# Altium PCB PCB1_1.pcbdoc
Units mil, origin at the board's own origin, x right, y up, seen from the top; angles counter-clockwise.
Board outline 85455 x 37379.02 mil, 2 copper layers (Top Layer, Bottom Layer); 14 components, 17 nets, 60 pads, 2 vias.
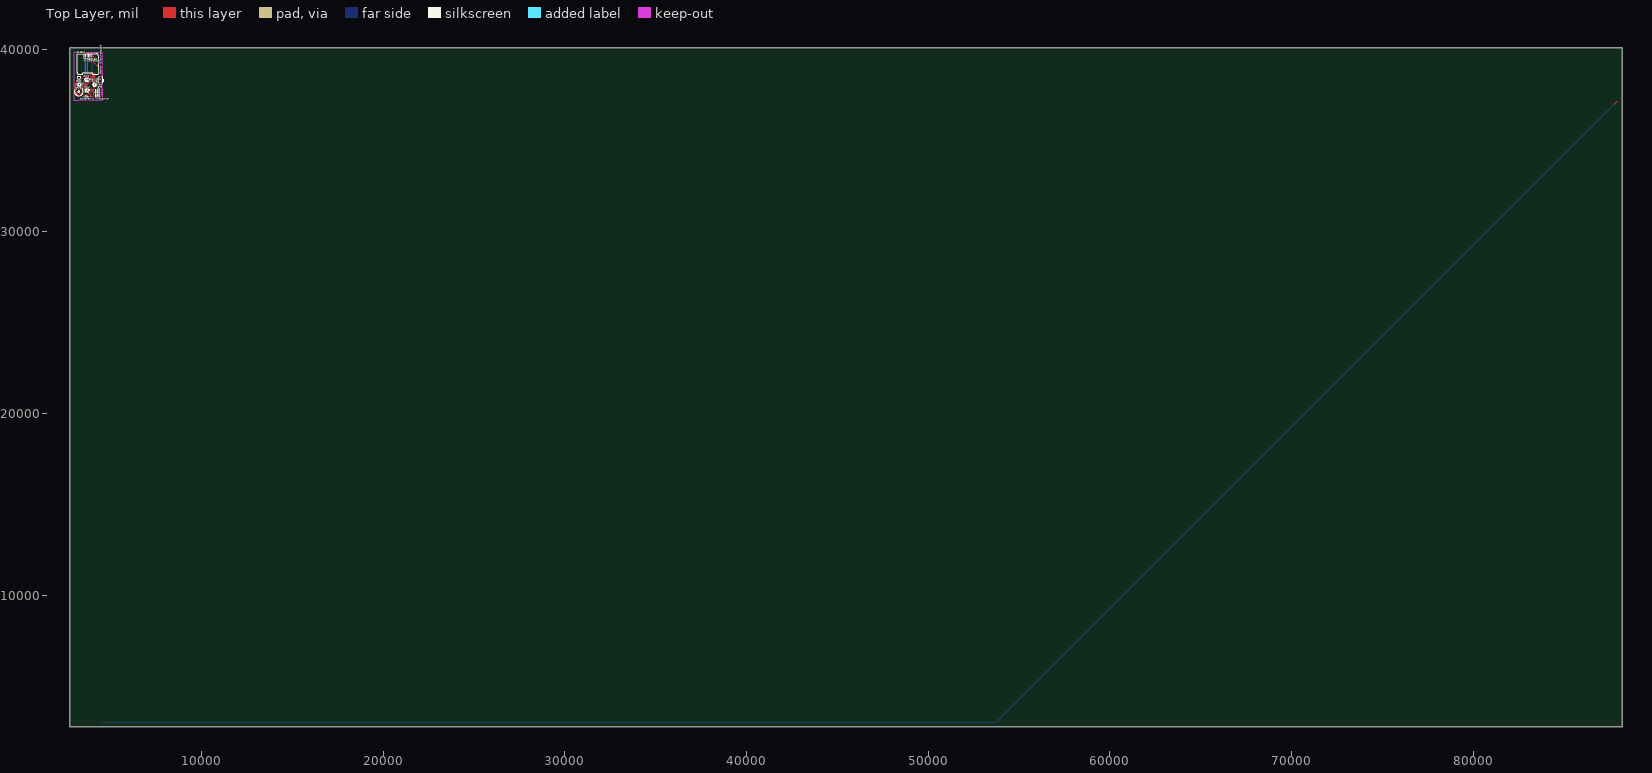
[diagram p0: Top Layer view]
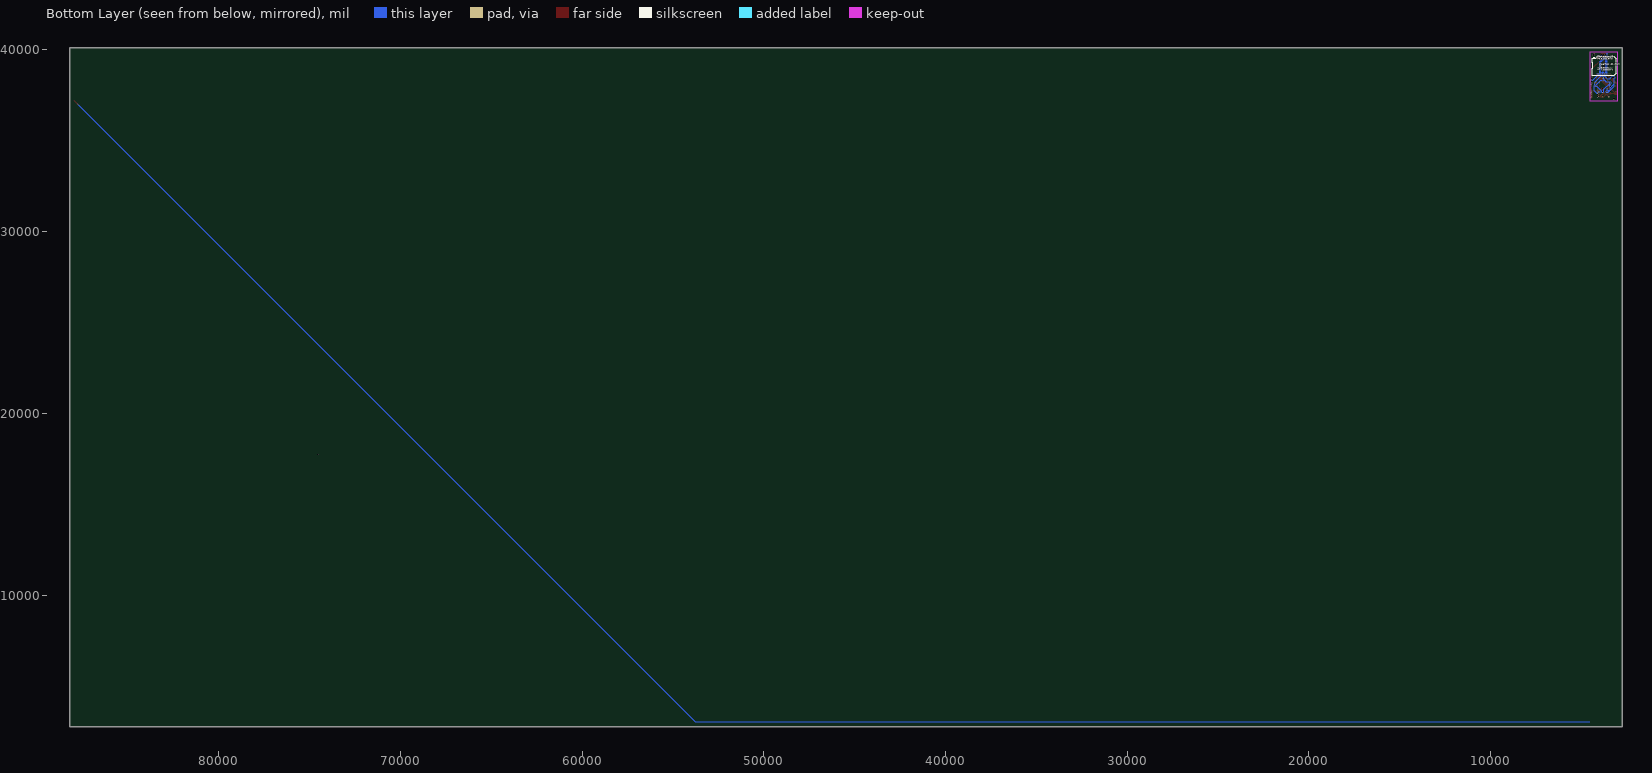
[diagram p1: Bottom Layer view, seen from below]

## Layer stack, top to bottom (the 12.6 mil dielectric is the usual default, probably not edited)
Top Layer: signal copper (thickness not stored)
Dielectric: dielectric 12.6, FR-4, Dk 4.8
Bottom Layer: signal copper (thickness not stored)

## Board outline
88205,2750 2750,2750 2750,40129.02 88205,40129.02

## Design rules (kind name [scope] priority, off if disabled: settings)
BoardOutlineClearance copperThickness1oz [All] p0: genericclearance=10 ignorepadtopadclearanceinfootprint=FALSE except(0: Arc-SplitContinuation Track-SplitContinuation SMDPad-SplitContinuation THPad-SplitContinuation Via-SplitContinuation Fill-SplitContinuation Poly-SplitContinuation Region-SplitContinuation Text-SplitContinuation; 6: Track-CutoutEdge SMDPad-CutoutEdge THPad-CutoutEdge Via-CutoutEdge Region-CutoutEdge; 11.8: Track-OutlineEdge SMDPad-OutlineEdge THPad-OutlineEdge Via-OutlineEdge Fill-OutlineEdge Region-OutlineEdge Poly-OutlineEdge Text-OutlineEdge Fill-CutoutEdge)
BoardOutlineClearance copperThickness2oz [All] p0: genericclearance=10 ignorepadtopadclearanceinfootprint=FALSE except(0: Arc-SplitContinuation Track-SplitContinuation SMDPad-SplitContinuation THPad-SplitContinuation Via-SplitContinuation Fill-SplitContinuation Poly-SplitContinuation Region-SplitContinuation Text-SplitContinuation; 6: Track-CutoutEdge SMDPad-CutoutEdge THPad-CutoutEdge Via-CutoutEdge Region-CutoutEdge; 11.8: Track-OutlineEdge SMDPad-OutlineEdge THPad-OutlineEdge Via-OutlineEdge Fill-OutlineEdge Region-OutlineEdge Poly-OutlineEdge Text-OutlineEdge Fill-CutoutEdge)
Clearance copperThickness1oz [(InNet('$1N1066') OR InNet('$1N1061') OR InNet('$1N1091') OR InNet('$1N1287') OR InNet('$1N1278') OR InNet('$1N1307') OR InNet('$1N1282') OR InNet('$1N1191') OR InNet('$1N1201') OR InNet('$1N1207') OR InNet('$1N1214') OR InNet('$1N1312') OR InNet('$1N2195') OR InNet('$1N2197') OR InNet('$1N2199') OR InNet('$1N2201') OR InNet('$1N2203'))] p1: gap=7 ignorepadtopadclearanceinfootprint=FALSE except(4: Track-Track; 6: Track-SMDPad SMDPad-SMDPad Track-THPad SMDPad-THPad THPad-THPad Track-Via SMDPad-Via THPad-Via Via-Via SMDPad-Fill THPad-Fill Via-Fill Fill-Fill Track-Region SMDPad-Region THPad-Region Via-Region Region-Region Track-Poly SMDPad-Poly THPad-Poly Via-Poly Fill-Poly Region-Poly Poly-Poly Track-Text SMDPad-Text THPad-Text Via-Text Fill-Text Region-Text Poly-Text Text-Text; 6.9: Track-Hole SMDPad-Hole THPad-Hole Via-Hole Fill-Hole Region-Hole Poly-Hole Text-Hole Sheet-Hole; 11.8: Track-Fill Fill-Region Track-Sheet SMDPad-Sheet THPad-Sheet Via-Sheet Fill-Sheet Region-Sheet Poly-Sheet Text-Sheet)
Clearance copperThickness2oz [All] p1: gap=7 ignorepadtopadclearanceinfootprint=FALSE except(6: Track-SMDPad SMDPad-SMDPad Track-THPad SMDPad-THPad THPad-THPad Track-Via SMDPad-Via THPad-Via Via-Via SMDPad-Fill THPad-Fill Via-Fill Fill-Fill Track-Region SMDPad-Region THPad-Region Via-Region Region-Region Track-Poly SMDPad-Poly THPad-Poly Via-Poly Fill-Poly Region-Poly Poly-Poly Track-Text SMDPad-Text THPad-Text Via-Text Fill-Text Region-Text Poly-Text Text-Text; 6.9: Track-Hole SMDPad-Hole THPad-Hole Via-Hole Fill-Hole Region-Hole Poly-Hole Text-Hole Sheet-Hole; 8: Track-Track; 11.8: Track-Fill Fill-Region Track-Sheet SMDPad-Sheet THPad-Sheet Via-Sheet Fill-Sheet Region-Sheet Poly-Sheet Text-Sheet)
DiffPairsRouting differentialPair [All] p1: maxuncoupledlength=10 minlimit=6 maxlimit=6 mostfreqgap=6 toplayer_minwidth=5 toplayer_prefwidth=10 toplayer_maxwidth=100 bottomlayer_minwidth=5 bottomlayer_prefwidth=10 bottomlayer_maxwidth=100
PasteMaskExpansion pasteMaskExpansion [All] p1: expansion=0
PlaneConnect innerPlane [All] p1: planeconnectstyle=Relief reliefexpansion=20 reliefentries=4 reliefconductorwidth=10 reliefairgap=10
PolygonConnect copperRegion [All] p1: connectstyle=Relief reliefentries=4 reliefconductorwidth=10 polygonreliefangle="90 Angle" airgapwidth=10
RoutingVias viaSize [All] p1: viastyle="Through Hole" holewidth=12.0078 minholewidth=11.811 maxholewidth=248.0314 width=24.0158 minwidth=19.685 maxwidth=393.7008
SolderMaskExpansion solderMaskExpansion [All] p1: useseparateexpansions=TRUE expansion=2 expansionbottom=2
Width copperThickness1oz [All] p1: maxlimit=100 minlimit=5 preferedwidth=10
Width copperThickness2oz [All] p1: maxlimit=100 minlimit=8 preferedwidth=10

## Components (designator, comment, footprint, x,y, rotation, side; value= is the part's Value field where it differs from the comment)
OLED1 "0.96OLED_4P_MODULE_JX" 0.96OLED_4P 3740,39744.02 r0 top
Q1 "BC547B_C719806" TO-92-3_L4.9-W3.7-P1.27-L 3260,38484.02 r180 top
R1 "resistor" "Resistor 1/8w 7mm metal film" 4105,37794.02 r0 top
R2 "resistor" "Resistor 1/8w 7mm metal film" 4110,37679.02 r0 top
R3 "resistor" "Resistor 1/8w 7mm metal film" 4115,37559.02 r0 top
R4 "resistor" "Resistor 1/8w 7mm metal film" 4110,37434.02 r0 top
R5 "resistor" "Resistor 1/8w 7mm metal film" 3490,37424.02 r0 top
SW1 "MLD-TS-6X6X5-J" SW-TH_4P-L6.0-W6.0-P4.50-LS6.5 3700,38384.02 r0 top
SW2 "MLD-TS-6X6X5-J" SW-TH_4P-L6.0-W6.0-P4.50-LS6.5 3285,38094.02 r0 top
SW3 "MLD-TS-6X6X5-J" SW-TH_4P-L6.0-W6.0-P4.50-LS6.5 4130,38104.02 r0 top
SW4 "MLD-TS-6X6X5-J" SW-TH_4P-L6.0-W6.0-P4.50-LS6.5 3715,37794.02 r0 top
SW5 "SK12D07VG4" SW-TH_SK12D07VG4 4445,38349.02 r90 top
U1 "_x001F_BEEF-12095" BUZ-TH_BD12.0-P7.60-D0.6-FD 3250,37714.02 r0 top
"wemos d1 mini" "WEMOS D1 MINI" "WEMOS D1 MINI" 4090,39574.02 r180 bottom

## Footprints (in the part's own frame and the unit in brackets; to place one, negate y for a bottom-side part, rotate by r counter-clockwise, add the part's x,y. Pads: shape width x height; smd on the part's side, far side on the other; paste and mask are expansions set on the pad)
0.96OLED_4P [mm]
  round 1.65 hole 1 copper offset 0,0: 1(-3.81,-0.001) 2(-1.27,0.002) 3(1.27,0.002) 4(3.81,0.002)
  silkscreen extent -15,-27.5 15,1.5
BUZ-TH_BD12.0-P7.60-D0.6-FD [mm]
  round 1.8 hole 1: 1(-3.8,0) 2(3.8,0)
  silkscreen extent -6,-6 6,6
"Resistor 1/8w 7mm metal film" [mm]
  round 2 hole 0.9: 1(0,0) 2(9,0)
  silkscreen extent 1.39,-1 7.64,1
SW-TH_4P-L6.0-W6.0-P4.50-LS6.5 [mm]
  round 1.8 hole 1.2: 1(-3.25,2.25) 2(3.25,2.25) 3(-3.25,-2.25) 4(3.25,-2.25)
  silkscreen extent -3,-3 3,3
SW-TH_SK12D07VG4 [mil]
  round 60 hole 36: 1(-78.74,0) 2(0,0) 3(78.74,0)
  oval 55.12x86.61 hole 31.5 slot 62.99 at 90 deg: 4(163.38,0) 5(-163.39,0)
  silkscreen extent -171,-191 171,87
TO-92-3_L4.9-W3.7-P1.27-L [mm]
  rect 0.9x1.6 hole 0.7: 1(-1.27,0)
  oval 0.9x1.6 hole 0.7: 2(0,0) 3(1.27,0)
  silkscreen extent -2.48,-1.5 2.48,2.48
"WEMOS D1 MINI" [mil]
  round 60 hole 36: 1(0,-899.99) 2(100,-899.99) 3(200,-899.99) 4(300,-899.99) 5(400,-899.99) 6(500,-899.99) 7(600,-899.99) 8(700,-899.99) 9(700,0.01) 10(600,0.01) 11(500,0.01) 12(400,0.01) 13(300,0.01) 14(200,0.01) 15(100,0.01) 16(0,0.01)
  silkscreen extent -354,-954 1000,54

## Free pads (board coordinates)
  round 122.05 hole 122.05: 1(4330,39744.02) 2(3215,37344.02)
  round 60 hole 0.1: 1(4485,37979.02) 2(4485,38074.02)

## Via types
v1: diameter 24.02, hole 12.01, Top Layer to Bottom Layer, 2 vias

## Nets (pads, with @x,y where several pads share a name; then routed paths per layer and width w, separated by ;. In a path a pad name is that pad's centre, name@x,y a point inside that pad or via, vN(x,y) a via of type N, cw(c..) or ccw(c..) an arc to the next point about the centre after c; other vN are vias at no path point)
$1N1061: "wemos d1 mini.6" OLED1.3 | length 1473.6
  Bottom Layer w10: 3590,38674.02 3590,39516.06 3630.99,39557.04 3630.99,39641.51 3546.54,39725.96 3546.54,39761.97 3572,39787.43 3608,39787.43 3633.46,39761.97 3633.46,39720.32 3654.79,39699 3744.93,39699 OLED1.3
$1N1066: "wemos d1 mini.5" OLED1.4 | length 1687.5
  Bottom Layer w10: 3690,38674.02 3830.98,38815 3949.02,38696.97 3949.02,38657.04 3973.02,38633.03 4006.98,38633.03 4030.99,38657.04 4030.99,38691 4004.02,38717.96 4004.02,39349.77 3890,39463.79 3890,39516.06 3849.02,39557.04 3849.02,39591 3890,39631.98 OLED1.4
$1N1091: "wemos d1 mini.16" OLED1.2 pad.2@4485,38074.02 R1.2 R2.2 R3.2 R4.2 SW5.2 | length 3491.9
  Top Layer w10: 4090,39574.02 3963.42,39700.6 3772,39700.6 3728.53,39744.07 OLED1.2 3687.5,39741.57 3687.5,39736.57 3841.52,39582.55 3841.52,39554.54 4481.79,38914.27 4481.79,38585.87 4486.79,38580.87 4486.79,38540.87 4499.29,38528.37 4499.29,38496.44 4486.79,38483.94 4486.79,38214.09 4499.29,38201.59 4499.29,38169.66 4437.5,38107.87 4437.5,37695.85 4456.83,37676.52 4461.83,37676.52 R2.2 R4.2
  Bottom Layer w10: SW5.2@4457.76,38364.02 4467.94,38364.02 4494.29,38337.66 4494.29,38206.59 4499.29,38201.59 4499.29,38169.66 4494.29,38164.66 4494.29,38141.27 4490,38136.98 4490,38079.02 pad.2@4485,38074.02
$1N1191: "wemos d1 mini.13" SW1.1 | length 1211.8
  Top Layer w10: SW1.1 3750,38650.55 3750,38656.06 3749.02,38657.04 3749.02,38691 3750,38691.98 3750,39566.95 3757.07,39574.02 3790,39574.02
$1N1201: "wemos d1 mini.14" SW2.1 | length 2771.3
  Top Layer w10: SW2.1 3646.54,38672.08 3646.54,39762.07 3672,39787.53 3908,39787.53 3933.46,39762.07 3933.46,39726.06 3944.91,39714.62 3969.22,39714.62 4068.84,39615 4106.98,39615 4130.99,39591 4130.99,39557.04 4106.98,39533.03 4073.02,39533.03 4049.02,39557.04 4049.02,39591 3981.71,39658.3 3897.43,39574.02 3890,39574.02
$1N1207: SW3.1
$1N1214: "wemos d1 mini.4" SW4.1 | length 2136.4
  Bottom Layer w10: SW4.1 3587.05,37771.08 3633.47,37724.66 3633.47,37686.21 3606.28,37659.02 3604.98,37659.02 3579.98,37634.02 3552.25,37634.02 3217.28,37968.98 3217.28,38422.36 3181.3,38458.35 3181.3,38509.68 3198.11,38526.5 3332.27,38526.5 3432.58,38426.18 3591.28,38426.18 3790,38624.9 3790,38674.02
$1N1278: Q1.2 R5.2 | length 2189.9
  Top Layer w10: Q1.2 3260,38371.01 3037,38148.01 3037,37586.95 3085.36,37538.58 3135.43,37538.58 3181.84,37585 3357.98,37585 3390.38,37552.6 3865.75,37552.6 3987.92,37430.43 3850.74,37430.43 R5.2
$1N1282: "wemos d1 mini.3" R5.1 | length 4226.2
  Top Layer w10: R5.1 3604.57,37538.58 3658.55,37538.58 3823.47,37373.66 3865.19,37373.66 3907.94,37416.41 3993.72,37416.41 4001.93,37424.62 4001.93,37436.23 3871.55,37566.61 3815.23,37566.61 3490,37891.84 4130.99,38532.83 4130.99,38691 4106.98,38715 4073.02,38715 4049.02,38691 4049.02,38601.97 3525.63,38078.58 3525.63,38314.66 3552.82,38341.85 3557.84,38341.85 3642.16,38426.18 3847.18,38426.18 3874.37,38453.37 3874.37,38658.39 3890,38674.02
$1N1287: Q1.3 SW4.3 | length 985.4
  Bottom Layer w10: Q1.3 3231.3,38462.72 3231.3,38121.44 3445,37907.74 3445,37761.09 3452.07,37754.02 3538.47,37754.02 SW4.3
$1N1307: Q1.1 U1.2 | length 1542.6
  Top Layer w10: Q1.1 3310,38362.74 3176.28,38229.01 3137.82,38229.01 3051.01,38142.2 3051.01,37592.75 3091.17,37552.6 3129.62,37552.6 3176.04,37599.02 3409.61,37599.02 3416.68,37606.09 3416.68,37656.94 3394.61,37679.02 U1.2@3394.61,37714.02
$1N1312: "wemos d1 mini.1" SW5.1 U1.1 | length 2268.3
  Top Layer w10: 3065.03,37704.02 3090.39,37704.02 U1.1@3097.89,37711.52 ; U1.1 U1.1@3097.89,37711.52 ; 4090,38674.02 4090,38578.62 3853.23,38341.85 3808.72,38341.85 3781.53,38314.66 3781.53,38270.15 3130.2,37618.82 3120.2,37618.82 3110,37629.02 3110,37699.41 U1.1@3097.89,37711.52
  Bottom Layer w10: 4090,38674.02 4072.5,38656.52 4072.5,38631.51 4407.08,38296.94 4453.35,38296.94 4453.35,38278.63 SW5.1 ; 4094.41,38674.02 4119.78,38699.38 4122.6,38699.38
$1N2195: "wemos d1 mini.2" OLED1.1 pad.1@4485,37979.02 SW1.4 SW2.4 SW3.4 SW4.4 | length 8039.9
  Top Layer w10: SW4.4 3842.95,37816.95 3796.53,37863.37 3796.53,37901.82 3823.72,37929.01 3862.18,37929.01 4047.53,37743.66 4370.19,37743.66 4413.98,37699.87 4413.98,37658.16 4448.47,37623.66 4448.47,37609.37 4418.98,37579.87 4418.98,37538.16 4443.47,37513.66 4443.47,37484.37 4413.98,37454.87 4413.98,37413.16 4443.47,37383.66 4485.19,37383.66 4514.68,37413.16 4514.68,37454.87 4490.19,37479.37 4490.19,37508.66 4519.68,37538.16 4519.68,37579.87 4485.19,37614.37 4485.19,37628.66 4514.68,37658.16 4514.68,37699.87 4480.19,37734.37 4480.19,37743.66 4509.68,37773.16 4509.68,37814.87 4485,37839.56 pad.1@4485,37979.02
  Bottom Layer w10: SW2.4 3412.95,38116.95 3366.53,38163.37 3366.53,38201.82 3393.72,38229.01 3611.56,38229.01 ; OLED1.1 3749.02,39584.95 3749.02,39557.04 3773.02,39533.03 3800.93,39533.03 3990,39343.96 3990,38685.98 ; SW4.4 4152.95,38015.44 SW3.4 3977.95,38295.44 SW1.4 3702.95,38295.44 3636.53,38229.01 3611.56,38229.01 ; 3990,38674.02 3990,38685.98 ; 3611.56,38229.01 3781.53,38398.99 3781.53,38491.82 3849.02,38559.31 3849.02,38680.25 3792.45,38736.82 3745,38689.38 3745,38651.24 3712.78,38619.02 3667.22,38619.02 3635,38651.24 3635,39495.01 3649.02,39509.03 3649.02,39591 3673.02,39615 3706.98,39615 3730.99,39591 3730.99,39552.86 3979.83,39304.01 3979.83,38696.15 3990,38685.98
$1N2197: R1.1 SW1.2 | length 1506.5
  Top Layer w10: SW1.2 3827.95,38635.98 3849.02,38657.04 3849.02,38691 3873.02,38715 3906.98,38715 3930.99,38691 3949.02,38691 3973.02,38715 4006.98,38715 4025.18,38696.8 4035,38696.8 4067.22,38729.02 4112.78,38729.02 4145,38696.8 4145,38053.31 4105,38013.31 R1.1
$1N2199: R2.1 SW2.2 | length 997
  Bottom Layer w10: SW2.2 3796.53,37799.01 3796.53,37686.21 3823.72,37659.02 3862.18,37659.02 3885.6,37682.44 3898.89,37682.44 3906,37689.55 3916.53,37679.02 R2.1
$1N2201: "wemos d1 mini.12" R3.1 SW3.2 | length 2686.9
  Bottom Layer w10: 3690,39574.02 3690,38731.98 3649.02,38691 3649.02,38657.04 3673.02,38633.03 3706.98,38633.03 3730.99,38657.04 3730.99,38695.18 3786.64,38750.84 3798.25,38750.84 3834.09,38715 3906.98,38715 3930.99,38691 3930.99,38553.03 4257.95,38226.07 SW3.2 4257.95,38081.08 4304.37,38034.66 4304.37,37748.38 R3.1
$1N2203: R4.1 SW4.2 | length 559.2
  Top Layer w10: SW4.2 4059.65,37665.9 4059.65,37543.16 4110,37492.8 R4.1
pads on no net: "wemos d1 mini.7" "wemos d1 mini.8" "wemos d1 mini.9" "wemos d1 mini.10" "wemos d1 mini.11" "wemos d1 mini.15" SW1.3 SW2.3 SW3.3 SW5.3 SW5.4 SW5.5
copper on no net: | length 97566.1
  Top Layer w10: v1(87750,37005) 87950,37205
  Bottom Layer w10: 4550,3005 53750,3005 v1(87750,37005)
  other v1: 74550,17735

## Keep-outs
Board Outline Layer:
  lines w10: 3000,37210 4545,37210 4545,39879.02 3000,39879.02 3000,37210

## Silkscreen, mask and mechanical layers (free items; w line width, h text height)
Top Silkscreen Layer:
  text "Github- @sasukeop108" at 4510,38674.02 h75 r90
  text "ClockX-V1" at 3835,38339.02 h100
  text "vcc" at 4295,38034.02 h100
  text "gnd" at 4300,37929.02 h100
  text "designed by sivasankar" at 3310,37259.02 h100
